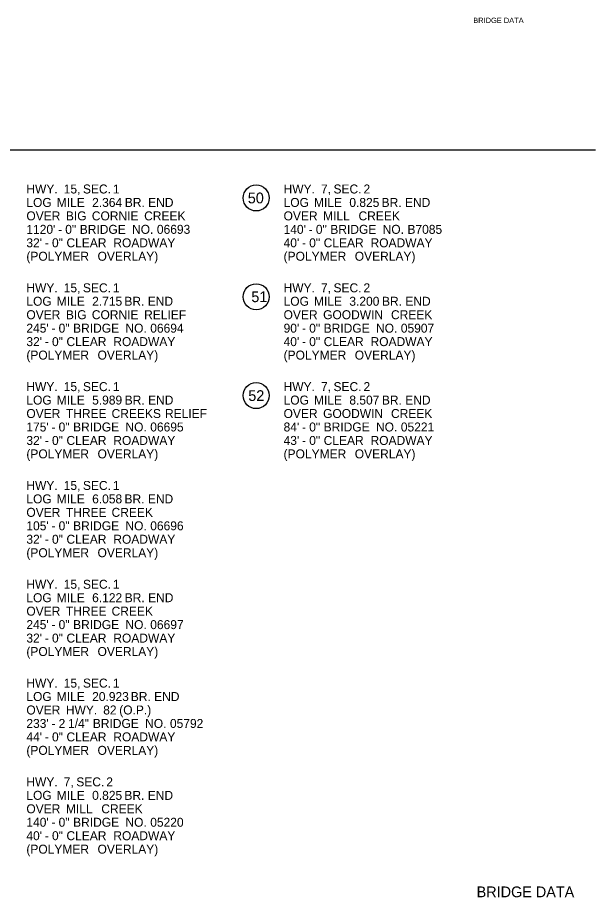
# Model space of a CAD drawing. Extents: x 1930546 to 1934225, y 596452 to 599536.
# Drawn here: x 1933581 to 1934225, y 598531 to 599512 of the extents above; entities that cross this region are included whole.
import ezdxf

# ---------------------------------------------------------------- set-up
doc = ezdxf.new("R2010")
doc.units = 0
for name, color, linetype in [('Default', 7, 'Continuous'), ('R_Border', 7, 'Continuous'), ('R_Border Prem', 7, 'Continuous')]:
    doc.layers.add(name, color=color, linetype=linetype)

msp = doc.modelspace()

# ---------------------------------------------------------------- linework, layer by layer
at = {"layer": 'R_Border'}
msp.add_line((1934224.56, 599363.54), (1932629.2, 599363.54), dxfattribs=at)
for centre in [(1933846.48, 599310.41), (1933846.48, 599200.23), (1933846.48, 599090.06)]:
    msp.add_circle(centre, 14.52, dxfattribs=at)

# ---------------------------------------------------------------- texts
at = {"layer": 'Default'}
for s, p in [('HWY.', (1933590.41, 599315.41)), (' 15,', (1933628.32, 599315.41)), (' SEC.', (1933649.72, 599315.41)), (' 1', (1933683.13, 599315.41)), ('HWY.', (1933877.06, 599315.41)), (' 7,', (1933914.97, 599315.41)), (' SEC.', (1933928.98, 599315.41)), (' 2', (1933962.39, 599315.41)), ('LOG', (1933590.41, 599300.41)), (' MILE', (1933620.54, 599300.41)), (' 2.364', (1933659.98, 599300.41)), (' BR.', (1933696.4, 599300.41)), (' END', (1933722.43, 599300.41)), ('LOG', (1933877.06, 599300.41)), (' MILE', (1933907.19, 599300.41)), (' 0.825', (1933946.63, 599300.41)), (' BR.', (1933982.58, 599300.41)), (' END', (1934008.62, 599300.41)), ('OVER', (1933590.41, 599285.41)), (' BIG', (1933630.74, 599285.41)), (' CORNIE', (1933659.64, 599285.41)), (' CREEK', (1933717.96, 599285.41)), ('OVER', (1933877.06, 599285.41)), (' MILL', (1933917.39, 599285.41)), (' CREEK', (1933956.85, 599285.41)), ("1120'", (1933590.41, 599270.41)), (' 0"', (1933630.02, 599270.41)), (' BRIDGE', (1933646.16, 599270.41)), (' NO.', (1933704.47, 599270.41)), (' 06693', (1933732.13, 599270.41)), ("140'", (1933877.06, 599270.41)), (' 0"', (1933909.29, 599270.41)), (' BRIDGE', (1933925.42, 599270.41)), (' NO.', (1933983.74, 599270.41)), (' B7085', (1934011.39, 599270.41)), ("32'", (1933590.41, 599255.41)), (' 0"', (1933615.25, 599255.41)), (' -', (1933622, 599270.41)), (' CLEAR', (1933631.38, 599255.41)), (' ROADWAY', (1933683.6, 599255.41)), ("40'", (1933877.06, 599255.41)), (' -', (1933901.26, 599270.41)), (' 0"', (1933901.9, 599255.41)), (' CLEAR', (1933918.03, 599255.41)), (' ROADWAY', (1933970.25, 599255.41)), (' -', (1933607.22, 599255.41)), (' -', (1933893.87, 599255.41)), ('(POLYMER', (1933590.41, 599240.41)), (' OVERLAY)', (1933666.01, 599240.41)), ('(POLYMER', (1933877.06, 599240.41)), (' OVERLAY)', (1933952.66, 599240.41)), ('HWY.', (1933590.41, 599205.23)), (' 15,', (1933628.32, 599205.23)), (' SEC.', (1933649.72, 599205.23)), (' 1', (1933683.13, 599205.23)), ('HWY.', (1933877.06, 599205.23)), (' 7,', (1933914.97, 599205.23)), (' SEC.', (1933928.98, 599205.23)), (' 2', (1933962.39, 599205.23)), ('LOG', (1933590.41, 599190.23)), (' MILE', (1933620.54, 599190.23)), (' 2.715', (1933659.98, 599190.23)), (' BR.', (1933695.93, 599190.23)), (' END', (1933721.97, 599190.23)), ('LOG', (1933877.06, 599190.23)), (' MILE', (1933907.19, 599190.23)), (' 3.200', (1933946.63, 599190.23)), (' BR.', (1933983.03, 599190.23)), (' END', (1934009.06, 599190.23)), ('OVER', (1933590.41, 599175.23)), (' BIG', (1933630.74, 599175.23)), (' CORNIE', (1933659.64, 599175.23)), (' RELIEF', (1933717.96, 599175.23)), ('OVER', (1933877.06, 599175.23)), (' GOODWIN', (1933917.39, 599175.23)), (' CREEK', (1933993.03, 599175.23)), ("245'", (1933590.41, 599160.23)), (' 0"', (1933622.64, 599160.23)), (' BRIDGE', (1933638.77, 599160.23)), (' NO.', (1933697.09, 599160.23)), (' 06694', (1933724.74, 599160.23)), ("90'", (1933877.06, 599160.23)), (' 0"', (1933901.9, 599160.23)), (' BRIDGE', (1933918.03, 599160.23)), (' NO.', (1933976.35, 599160.23)), (' 05907', (1934004.01, 599160.23)), (' -', (1933614.61, 599160.23)), (' -', (1933893.87, 599160.23)), ("32'", (1933590.41, 599145.23)), (' -', (1933607.22, 599145.23)), (' 0"', (1933615.25, 599145.23)), (' CLEAR', (1933631.38, 599145.23)), (' ROADWAY', (1933683.6, 599145.23)), ("40'", (1933877.06, 599145.23)), (' -', (1933893.87, 599145.23)), (' 0"', (1933901.9, 599145.23)), (' CLEAR', (1933918.03, 599145.23)), (' ROADWAY', (1933970.25, 599145.23)), ('(POLYMER', (1933590.41, 599130.23)), (' OVERLAY)', (1933666.01, 599130.23)), ('(POLYMER', (1933877.06, 599130.23)), (' OVERLAY)', (1933952.66, 599130.23)), ('HWY.', (1933590.41, 599095.06)), (' 15,', (1933628.32, 599095.06)), (' SEC.', (1933649.72, 599095.06)), (' 1', (1933683.13, 599095.06)), ('HWY.', (1933877.06, 599095.06)), (' 7,', (1933914.97, 599095.06)), (' SEC.', (1933928.98, 599095.06)), (' 2', (1933962.39, 599095.06)), ('LOG', (1933590.41, 599080.06)), (' MILE', (1933620.54, 599080.06)), (' 5.989', (1933659.98, 599080.06)), (' BR.', (1933696.28, 599080.06)), (' END', (1933722.31, 599080.06)), ('LOG', (1933877.06, 599080.06)), (' MILE', (1933907.19, 599080.06)), (' 8.507', (1933946.63, 599080.06)), (' BR.', (1933982.9, 599080.06)), (' END', (1934008.93, 599080.06)), ('OVER', (1933590.41, 599065.06)), (' THREE', (1933630.74, 599065.06)), (' CREEKS', (1933681.65, 599065.06)), (' RELIEF', (1933741.17, 599065.06)), ('OVER', (1933877.06, 599065.06)), (' GOODWIN', (1933917.39, 599065.06)), (' CREEK', (1933993.03, 599065.06)), ("175'", (1933590.41, 599050.06)), (' 0"', (1933622.64, 599050.06)), (' BRIDGE', (1933638.77, 599050.06)), (' NO.', (1933697.09, 599050.06)), (' 06695', (1933724.74, 599050.06)), ("84'", (1933877.06, 599050.06)), (' 0"', (1933901.9, 599050.06)), (' BRIDGE', (1933918.03, 599050.06)), (' NO.', (1933976.35, 599050.06)), (' 05221', (1934004.01, 599050.06)), (' -', (1933614.61, 599050.06)), (' -', (1933893.87, 599050.06)), ("32'", (1933590.41, 599035.06)), (' 0"', (1933615.25, 599035.06)), (' CLEAR', (1933631.38, 599035.06)), (' ROADWAY', (1933683.6, 599035.06)), ("43'", (1933877.06, 599035.06)), (' 0"', (1933901.9, 599035.06)), (' CLEAR', (1933918.03, 599035.06)), (' ROADWAY', (1933970.25, 599035.06)), ('(POLYMER', (1933590.41, 599020.06)), (' -', (1933607.22, 599035.06)), (' OVERLAY)', (1933666.01, 599020.06)), ('(POLYMER', (1933877.06, 599020.06)), (' -', (1933893.87, 599035.06)), (' OVERLAY)', (1933952.66, 599020.06)), ('HWY.', (1933590.41, 598984.88)), (' 15,', (1933628.32, 598984.88)), (' SEC.', (1933649.72, 598984.88)), (' 1', (1933683.13, 598984.88)), ('LOG', (1933590.41, 598969.88)), (' MILE', (1933620.54, 598969.88)), (' 6.058', (1933659.98, 598969.88)), (' BR.', (1933696.06, 598969.88)), (' END', (1933722.09, 598969.88)), ('OVER', (1933590.41, 598954.88)), (' THREE', (1933630.74, 598954.88)), (' CREEK', (1933681.65, 598954.88)), ("105'", (1933590.41, 598939.88)), (' -', (1933614.61, 598939.88)), (' 0"', (1933622.64, 598939.88)), (' BRIDGE', (1933638.77, 598939.88)), (' NO.', (1933697.09, 598939.88)), (' 06696', (1933724.74, 598939.88)), ("32'", (1933590.41, 598924.88)), (' 0"', (1933615.25, 598924.88)), (' CLEAR', (1933631.38, 598924.88)), (' ROADWAY', (1933683.6, 598924.88)), (' -', (1933607.22, 598924.88)), ('(POLYMER', (1933590.41, 598909.88)), (' OVERLAY)', (1933666.01, 598909.88)), ('HWY.', (1933590.41, 598874.71)), (' 15,', (1933628.32, 598874.71)), (' SEC.', (1933649.72, 598874.71)), (' 1', (1933683.13, 598874.71)), ('LOG', (1933590.41, 598859.71)), (' MILE', (1933620.54, 598859.71)), (' 6.122', (1933659.98, 598859.71)), (' BR.', (1933696.29, 598859.71)), (' END', (1933722.32, 598859.71)), ('OVER', (1933590.41, 598844.71)), (' THREE', (1933630.74, 598844.71)), (' CREEK', (1933681.65, 598844.71)), ("245'", (1933590.41, 598829.71)), (' -', (1933614.61, 598829.71)), (' 0"', (1933622.64, 598829.71)), (' BRIDGE', (1933638.77, 598829.71)), (' NO.', (1933697.09, 598829.71)), (' 06697', (1933724.74, 598829.71)), ("32'", (1933590.41, 598814.71)), (' 0"', (1933615.25, 598814.71)), (' CLEAR', (1933631.38, 598814.71)), (' ROADWAY', (1933683.6, 598814.71)), (' -', (1933607.22, 598814.71)), ('(POLYMER', (1933590.41, 598799.71)), (' OVERLAY)', (1933666.01, 598799.71)), ('HWY.', (1933590.41, 598764.53)), (' 15,', (1933628.32, 598764.53)), (' SEC.', (1933649.72, 598764.53)), (' 1', (1933683.13, 598764.53)), ('LOG', (1933590.41, 598749.53)), (' MILE', (1933620.54, 598749.53)), (' 20.923', (1933659.98, 598749.53)), (' BR.', (1933703.07, 598749.53)), (' END', (1933729.1, 598749.53)), ('OVER', (1933590.41, 598734.53)), (' HWY.', (1933630.74, 598734.53)), (' 82', (1933672.33, 598734.53)), (' (O.P.)', (1933690.18, 598734.53)), ("233'", (1933590.41, 598719.53)), (' 2', (1933622.64, 598719.53)), (' 1/4"', (1933633.1, 598719.53)), (' BRIDGE', (1933660.73, 598719.53)), (' NO.', (1933719.04, 598719.53)), (' 05792', (1933746.7, 598719.53)), (' -', (1933614.61, 598719.53)), ("44'", (1933590.41, 598704.53)), (' -', (1933607.22, 598704.53)), (' 0"', (1933615.25, 598704.53)), (' CLEAR', (1933631.38, 598704.53)), (' ROADWAY', (1933683.6, 598704.53)), ('(POLYMER', (1933590.41, 598689.53)), (' OVERLAY)', (1933666.01, 598689.53)), ('HWY.', (1933590.41, 598654.36)), (' 7,', (1933628.32, 598654.36)), (' SEC.', (1933642.33, 598654.36)), (' 2', (1933675.74, 598654.36)), ('LOG', (1933590.41, 598639.36)), (' MILE', (1933620.54, 598639.36)), (' 0.825', (1933659.98, 598639.36)), (' BR.', (1933695.93, 598639.36)), (' END', (1933721.97, 598639.36)), ('OVER', (1933590.41, 598624.36)), (' MILL', (1933630.74, 598624.36)), (' CREEK', (1933670.2, 598624.36)), ("140'", (1933590.41, 598609.36)), (' 0"', (1933622.64, 598609.36)), (' BRIDGE', (1933638.77, 598609.36)), (' NO.', (1933697.09, 598609.36)), (' 05220', (1933724.74, 598609.36)), (' -', (1933614.61, 598609.36)), ("40'", (1933590.41, 598594.36)), (' -', (1933607.22, 598594.36)), (' 0"', (1933615.25, 598594.36)), (' CLEAR', (1933631.38, 598594.36)), (' ROADWAY', (1933683.6, 598594.36)), ('(POLYMER', (1933590.41, 598579.36)), (' OVERLAY)', (1933666.01, 598579.36))]:
    msp.add_text(s, height=10, rotation=360, dxfattribs=at).set_placement(p)
at = {"layer": 'R_Border'}
for s, p in [('50', (1933837.18, 599304.41)), ('51', (1933841.1, 599194.23)), ('52', (1933837.7, 599084.06)), ('BRIDGE DATA', (1934092.22, 598530.75))]:
    msp.add_text(s, height=12, rotation=360, dxfattribs=at).set_placement(p)
at = {"layer": 'R_Border Prem'}
msp.add_text('BRIDGE DATA', height=6, rotation=360, dxfattribs=at).set_placement((1934088.44, 599505.41))

doc.saveas('drawing.dxf')
